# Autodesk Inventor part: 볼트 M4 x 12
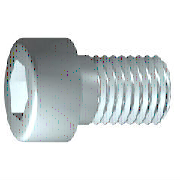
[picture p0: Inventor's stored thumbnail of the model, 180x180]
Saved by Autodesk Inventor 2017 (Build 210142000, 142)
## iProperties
IsCustomPart: 0
Created: 2012-02
Part Number: 볼트 M4 x 12
Material: 스테인리스강
Description: 6각 소켓 머리 캡 나사
Document SubType Name: Modeling
Standard: ISO 4762
Designer: mduedu
Standard Revision: Fourth edition 2004-03-01
Standards Organization: ISO
Language: ko-KR
Size Designation: M4 x 8
Categories: <MemberInstance><Categories><Category DisplayName="조임쇠" InternalName="e4da775c-781d-43d5-af7c-5136215cf5a6" Mnemonic="FSTN"><Category DisplayName="볼트" InternalN
Density: 8.08 g/cm^3
Mass: 2.29719 g
Surface Area: 3.30853 cm^2
Volume: 0.284306 cm^3
Appearance: 반광택
Author: mduedu
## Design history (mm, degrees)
sketch "스케치1"
  geometry: L1 (-1, 0)-(12, 0); L2 (12, 0)-(12, 2); L3 (12, 2)-(1.75, 2); L4 (1.75, 2)-(1.32, 2); L5 (1.32, 2)-(0, 2); L6 (0, 2)-(0, 3.5); L7 (0, 3.5)-(-4, 3.5); L8 (-4, 3.5)-(-4, 1.732); L9 (-4, 1.732)-(-2, 1.732); L10 (-2, 1.732)-(-1, 0); L11 (-7.2, 0)-(15.2, 0) reference; L12 (0, -0.7)-(0, 4.2) reference; L13 (1.75, 2)-(0, 2)
  constraints: 22 end point, 6 parallel, 2 collinear, 2 perpendicular, 1 horizontal, 1 point on line
  dimensions: "d1" = 10.25 distance from line of L3.end L2 (= GEL); "d2" = 0.42952 distance of L4.end L3.end (computed from GAL); "d3" = 4 distance between parallel lines of L8 L6 (= KOH); "d4" = 2 distance of L8.end L9.end (= INTI); "d5" = 60 deg angle of L10 L1; "d6" = 4 diameter of L3 L1 (= GD); "d7" = 4 diameter of L5 L1 (= BDM); "d8" = 3.4641 diameter of L9 L1 (= 1.1547 x SW); "d9" = 7 diameter of L7 L1 (= KOD); "d26" = 12 distance between parallel lines of L12 L2 (= NLG)
revolve "본체" sketch "스케치1" stored, may be unused: angle "d10" = 90 deg
sketch "스케치2"
  geometry: L1 (0, -4.9)-(0, 4.9) reference; L2 (-4.9, 0)-(4.9, 0) reference; L3 (1.732, 0)-(0.866, -1.5); L4 (0.866, -1.5)-(-0.866, -1.5); L5 (-0.866, -1.5)-(-1.732, 0); L6 (-1.732, 0)-(-0.866, 1.5); L7 (-0.866, 1.5)-(0.866, 1.5); L8 (0.866, 1.5)-(1.732, 0); 2 further points
  constraints: 12 end point, 1 coincident, 1 horizontal alignment, 1 point on line, 12 other
extrude "슬롯" join sketch "스케치2" stored distance "d11" = 10; taper "d12" = 0 deg
workplane "Work Plane1"
fillet "Fillet2" dims "d30" = 0.1 (= R)
body "Solid1"
fillet "모깎기1" dims "d17" = 0.4 (= RR)
feature "스레드" dims "d13" = 10.25 (= GEL), "d14" = 0
chamfer "모따기1" distance "d15" = 0.42941 (= -0.5 x SPD + 0.5 x GD); stored, may be unused: second distance "d16" = 0.42941 (= GUL), angle "d27" = 45 deg
other parameters: "GD" = 4 [user parameter; used in 2 equation terms], "NLG" = 12 [user parameter; used in 1 equation term], "GEL" = 10.25 [user parameter; used in 2 equation terms], "KOD" = 7 [user parameter; used in 1 equation term], "KOH" = 4 [user parameter; used in 1 equation term], "INTI" = 2 [user parameter; used in 1 equation term], "GAL" = 0.42941 (= 0.61345 x PTC) [user parameter; used in 1 equation term], "GUL" = 0.42941 (= 0.61345 x PTC) [user parameter; used in 1 equation term], "BDM" = 4 (= NND) [user parameter; used in 1 equation term], "SW" = 3 [user parameter; used in 2 equation terms], "RR" = 0.4 [user parameter; used in 1 equation term], "SPD" = 3.14117 (= NND - 1.2269 x PTC) [user parameter; used in 1 equation term], "d19" = 0, "d28" = 0, "d29" = 0, "R" = 0.1 [user parameter; used in 1 equation term], "TOA" = 30 deg [user parameter], "GD1" = 3.14117 (= THREADDIA - 1.2269 x PTC) [user parameter], "THREADDIA" = 4 [user parameter; used in 1 equation term], "FAWI" = 45 deg [user parameter], "TPU" = 14.28571 (computed from PTC) [user parameter], "PTC" = 0.7 [user parameter; used in 5 equation terms], "NND" = 4 [user parameter; used in 2 equation terms], "E0" = 3.465 (= 1.155 x SW) [user parameter]
